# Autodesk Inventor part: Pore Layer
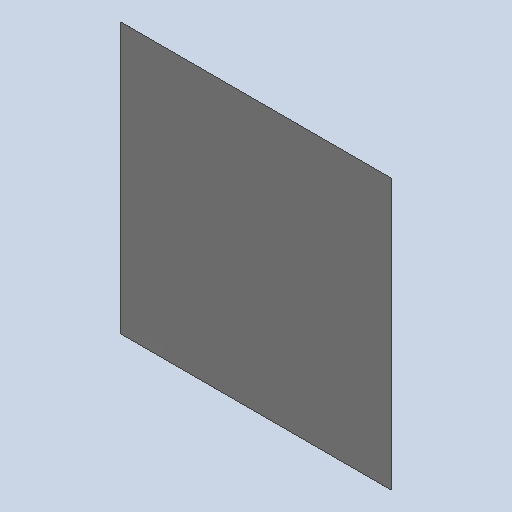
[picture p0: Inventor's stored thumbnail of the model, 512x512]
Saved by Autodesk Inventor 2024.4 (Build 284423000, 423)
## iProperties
Created: 2025-08
Part Number: Pore Layer
Material: Generic
Document SubType Name: Modeling
Designer: AdminForWorker
Density: 1 g/cm^3
Appearance: Default
Title: Pore Layer
Author: AdminForWorker
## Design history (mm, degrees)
feature "Body1"
body "Solid1"
